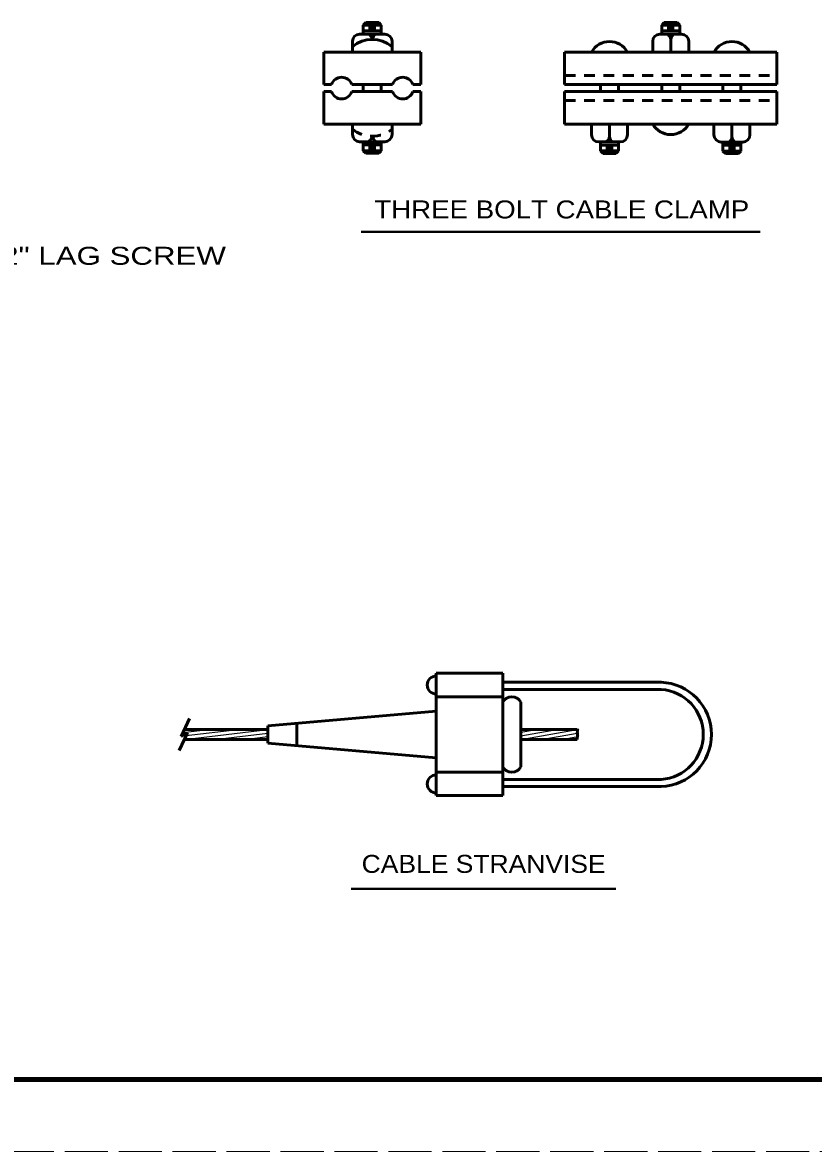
# Model space of a CAD drawing. Extents: x 12366 to 13046, y 9129 to 9570.
# Drawn here: x 12636.6 to 12746.6, y 9129.5 to 9286.4 of the extents above; entities that cross this region are included whole.
import ezdxf
from ezdxf.enums import TextEntityAlignment as Align

# ---------------------------------------------------------------- set-up
doc = ezdxf.new("R2010")
doc.units = 0
doc.linetypes.add('LONG_DASHED', pattern=[7.5, 6, -1.5])
doc.linetypes.add('SHORT_DASHED', pattern=[2.7, 1.5, -1.2])
doc.layers.add('1', color=7, linetype='Continuous', lineweight=53)
doc.layers.add('61', color=7, linetype='Continuous', lineweight=35)

msp = doc.modelspace()

# ---------------------------------------------------------------- linework, layer by layer
at = {"layer": '1'}
for p, q in [((12683.99, 9286.07), (12684.344, 9286.423)), ((12683.99, 9286.07), (12686.49, 9286.07)), ((12683.99, 9284.82), (12683.99, 9286.07)), ((12684.344, 9286.423), (12686.137, 9286.423)), ((12684.74, 9285.67), (12685.74, 9285.67)), ((12686.49, 9286.07), (12686.137, 9286.423)), ((12686.49, 9284.82), (12686.49, 9286.07)), ((12725.49, 9286.07), (12725.844, 9286.423)), ((12725.49, 9284.82), (12725.49, 9286.07)), ((12725.49, 9286.07), (12727.99, 9286.07)), ((12725.844, 9286.423), (12727.637, 9286.423)), ((12726.24, 9285.67), (12727.24, 9285.67)), ((12727.99, 9286.07), (12727.637, 9286.423)), ((12727.99, 9284.82), (12727.99, 9286.07)), ((12683.49, 9284.82), (12686.99, 9284.82)), ((12683.99, 9285.27), (12686.49, 9285.27)), ((12726.74, 9284.82), (12725.24, 9284.82)), ((12725.49, 9285.27), (12727.99, 9285.27)), ((12726.74, 9284.82), (12728.24, 9284.82)), ((12726.74, 9282.32), (12726.74, 9284.07)), ((12682.49, 9282.32), (12682.49, 9283.82)), ((12687.99, 9282.32), (12687.99, 9283.82)), ((12724.24, 9282.32), (12724.24, 9283.82)), ((12729.24, 9282.32), (12729.24, 9283.82)), ((12678.49, 9282.32), (12691.99, 9282.32)), ((12678.49, 9282.32), (12678.49, 9277.82)), ((12691.99, 9282.32), (12691.99, 9277.82)), ((12711.99, 9282.32), (12741.49, 9282.32)), ((12711.99, 9282.32), (12711.99, 9277.82)), ((12741.49, 9282.32), (12741.49, 9277.82)), ((12678.49, 9277.82), (12679.572, 9277.82)), ((12682.4, 9277.82), (12688.07, 9277.82)), ((12683.99, 9276.82), (12683.99, 9277.82)), ((12686.49, 9276.82), (12686.49, 9277.82)), ((12691.99, 9277.82), (12690.896, 9277.82)), ((12711.99, 9277.82), (12741.49, 9277.82)), ((12716.99, 9276.82), (12716.99, 9277.82)), ((12719.49, 9276.82), (12719.49, 9277.82)), ((12725.49, 9276.82), (12725.49, 9277.82)), ((12727.99, 9276.82), (12727.99, 9277.82)), ((12733.99, 9276.82), (12733.99, 9277.82)), ((12736.49, 9276.82), (12736.49, 9277.82)), ((12678.49, 9272.32), (12678.49, 9276.82)), ((12678.49, 9276.82), (12679.571, 9276.82)), ((12682.4, 9276.82), (12688.068, 9276.82)), ((12691.99, 9276.82), (12690.898, 9276.82)), ((12691.99, 9272.32), (12691.99, 9276.82)), ((12711.99, 9276.82), (12711.99, 9272.32)), ((12741.49, 9276.82), (12741.49, 9272.32)), ((12678.49, 9272.32), (12691.99, 9272.32)), ((12682.49, 9272.361), (12682.49, 9270.861)), ((12687.99, 9272.361), (12687.99, 9270.861)), ((12711.99, 9272.32), (12741.49, 9272.32)), ((12715.727, 9272.327), (12715.727, 9270.827)), ((12718.227, 9272.327), (12718.227, 9270.577)), ((12720.727, 9272.327), (12720.727, 9270.827)), ((12732.759, 9272.316), (12732.759, 9270.816)), ((12735.259, 9272.316), (12735.259, 9270.566)), ((12737.759, 9272.316), (12737.759, 9270.816)), ((12683.49, 9269.861), (12686.99, 9269.861)), ((12683.99, 9269.861), (12683.99, 9268.611)), ((12686.49, 9269.861), (12686.49, 9268.611)), ((12683.99, 9269.411), (12686.49, 9269.411)), ((12683.99, 9268.611), (12684.344, 9268.257)), ((12683.99, 9268.611), (12686.49, 9268.611)), ((12684.74, 9269.011), (12685.74, 9269.011)), ((12686.49, 9268.611), (12686.137, 9268.257)), ((12718.227, 9269.827), (12716.727, 9269.827)), ((12716.977, 9269.827), (12716.977, 9268.577)), ((12716.977, 9269.377), (12719.477, 9269.377)), ((12716.977, 9268.577), (12717.33, 9268.223)), ((12716.977, 9268.577), (12719.477, 9268.577)), ((12717.727, 9268.977), (12718.727, 9268.977)), ((12718.227, 9269.827), (12719.727, 9269.827)), ((12719.477, 9268.577), (12719.123, 9268.223)), ((12719.477, 9269.827), (12719.477, 9268.577)), ((12735.259, 9269.816), (12733.759, 9269.816)), ((12734.009, 9269.816), (12734.009, 9268.566)), ((12734.009, 9269.366), (12736.509, 9269.366)), ((12734.009, 9268.566), (12734.363, 9268.213)), ((12734.009, 9268.566), (12736.509, 9268.566)), ((12734.759, 9268.966), (12735.759, 9268.966)), ((12735.259, 9269.816), (12736.759, 9269.816)), ((12736.509, 9268.566), (12736.156, 9268.213)), ((12736.509, 9269.816), (12736.509, 9268.566)), ((12684.344, 9268.257), (12686.137, 9268.257)), ((12717.33, 9268.223), (12719.123, 9268.223)), ((12734.363, 9268.213), (12736.156, 9268.213)), ((12694.145, 9195.961), (12703.395, 9195.961)), ((12694.145, 9192.711), (12694.145, 9195.961)), ((12703.395, 9178.961), (12703.395, 9195.961)), ((12703.395, 9194.711), (12725.395, 9194.711)), ((12703.395, 9193.711), (12725.395, 9193.711)), ((12694.145, 9192.711), (12703.395, 9192.711)), ((12705.895, 9182.961), (12705.895, 9191.961)), ((12694.145, 9190.711), (12670.735, 9188.663)), ((12658.676, 9187.197), (12659.838, 9189.689)), ((12670.735, 9188.663), (12670.735, 9186.259)), ((12674.735, 9189.013), (12674.735, 9185.909)), ((12658.416, 9185.214), (12659.578, 9187.707)), ((12658.676, 9187.197), (12659.578, 9187.707)), ((12670.735, 9188.163), (12659.126, 9188.163)), ((12670.735, 9186.759), (12659.136, 9186.759)), ((12705.895, 9188.163), (12713.735, 9188.163)), ((12705.895, 9186.759), (12713.735, 9186.759)), ((12694.145, 9184.211), (12670.735, 9186.259)), ((12694.145, 9182.211), (12703.395, 9182.211)), ((12703.395, 9181.211), (12725.395, 9181.211)), ((12694.145, 9178.961), (12703.395, 9178.961)), ((12703.395, 9180.211), (12725.395, 9180.211))]:
    msp.add_line(p, q, dxfattribs=at)
at = {"layer": '1', "lineweight": 13}
msp.add_line((12682.407, 9277.82), (12682.49, 9277.82), dxfattribs=at)
at = {"layer": '1', "linetype": 'SHORT_DASHED'}
for p, q in [((12711.99, 9279.07), (12741.49, 9279.07)), ((12711.99, 9275.57), (12741.49, 9275.57))]:
    msp.add_line(p, q, dxfattribs=at)
at = {"layer": '1', "lineweight": 40}
for p, q in [((12683.688, 9257.318), (12739.159, 9257.318)), ((12682.314, 9166.003), (12719.09, 9166.003))]:
    msp.add_line(p, q, dxfattribs=at)
at = {"layer": '1', "lineweight": 25}
for p, q in [((12658.929, 9187.741), (12662.412, 9188.163)), ((12659.136, 9186.759), (12670.735, 9188.163)), ((12659.385, 9187.293), (12666.573, 9188.163)), ((12663.298, 9186.759), (12670.735, 9187.659)), ((12667.459, 9186.759), (12670.735, 9187.155)), ((12705.895, 9186.759), (12713.735, 9188.163)), ((12705.895, 9187.775), (12708.061, 9188.163)), ((12705.895, 9187.267), (12710.898, 9188.163)), ((12708.732, 9186.759), (12713.721, 9187.652)), ((12711.569, 9186.759), (12713.807, 9187.16))]:
    msp.add_line(p, q, dxfattribs=at)
at = {"layer": '1'}
for points in [[(12711.99, 9276.82), (12716.99, 9276.82), (12719.49, 9276.82), (12733.99, 9276.82)], [(12733.99, 9276.82), (12736.49, 9276.82), (12741.49, 9276.82)], [(12694.145, 9178.961), (12694.145, 9182.211), (12694.145, 9192.711)]]:
    msp.add_lwpolyline(points, dxfattribs=at)
for centre, radius, start, end in [((12683.49, 9283.82), 1, 90, 180), ((12685.24, 9279.789), 4.281, 50.03379, 129.96621), ((12683.913, 9283.727), 1.371, 14.49718, 52.88295), ((12686.561, 9283.727), 1.371, 127.11705, 165.50282), ((12686.99, 9283.82), 1, 0, 90), ((12725.24, 9283.82), 1, 90, 180), ((12725.86, 9284.025), 0.882, 2.94427, 64.43586), ((12727.621, 9284.025), 0.882, 115.56414, 177.05572), ((12728.24, 9283.82), 1, 0, 90), ((12718.227, 9280.933), 2.862, 29.14172, 150.85828), ((12735.259, 9280.922), 2.862, 29.14172, 150.85828), ((12680.986, 9277.319), 1.5, 19.49795, 160.50177), ((12689.483, 9277.317), 1.5, 19.58943, 160.41041), ((12680.986, 9277.319), 1.5, 199.44421, 340.55538), ((12689.483, 9277.317), 1.5, 199.35299, 340.6469), ((12726.74, 9273.714), 2.862, 209.14172, 330.85828), ((12683.49, 9270.861), 1, 180, 270), ((12683.913, 9270.954), 1.371, 307.11705, 345.50282), ((12686.561, 9270.954), 1.371, 194.49718, 232.88295), ((12686.99, 9270.861), 1, 270, 0), ((12716.727, 9270.827), 1, 180, 270), ((12717.346, 9270.622), 0.882, 295.56414, 357.05572), ((12719.107, 9270.622), 0.882, 182.94427, 244.43586), ((12719.727, 9270.827), 1, 270, 0), ((12733.759, 9270.816), 1, 180, 270), ((12734.379, 9270.611), 0.882, 295.56414, 357.05572), ((12736.14, 9270.611), 0.882, 182.94427, 244.43586), ((12736.759, 9270.816), 1, 270, 0), ((12694.145, 9194.336), 1.25, 90, 270), ((12725.141, 9187.461), 7.255, 272.01017, 87.98983), ((12725.002, 9187.461), 6.262, 273.59778, 86.40223), ((12704.645, 9191.294), 1.417, 28.07249, 151.92751), ((12704.645, 9183.626), 1.417, 208.07249, 331.92751), ((12694.145, 9180.586), 1.25, 90, 270)]:
    msp.add_arc(centre, radius, start, end, dxfattribs=at)
at = {"layer": '1', "lineweight": 13}
msp.add_arc((12680.986, 9277.319), 1.5, 199.26221, 340.15338, dxfattribs=at)
at = {"layer": '1', "linetype": 'SHORT_DASHED'}
msp.add_arc((12685.24, 9274.892), 4.281, 230.03379, 309.96621, dxfattribs=at)
at = {"layer": '1'}
msp.add_spline([(12713.735, 9188.163), (12713.818, 9188.028), (12713.754, 9187.932), (12713.775, 9187.783), (12713.722, 9187.655), (12713.807, 9187.548), (12713.764, 9187.452), (12713.796, 9187.27), (12713.786, 9187.121), (12713.722, 9187.003), (12713.732, 9186.939), (12713.735, 9186.759)], degree=3, dxfattribs=at)
at = {"layer": '61', "lineweight": 158}
msp.add_line((13035.052, 9139.493), (12395.992, 9139.513), dxfattribs=at)
at = {"layer": '61', "linetype": 'LONG_DASHED', "lineweight": 13}
msp.add_line((13045.992, 9129.513), (12365.932, 9129.493), dxfattribs=at)

# ---------------------------------------------------------------- texts
at = {"layer": '1'}
for s, width, p in [('THREE BOLT CABLE CLAMP', 1.15, (12711.593, 9259.197)), ('CABLE STRANVISE', 1.1, (12700.729, 9168.218))]:
    msp.add_text(s, height=2.5, dxfattribs=dict(at, width=width)).set_placement(p, align=Align.CENTER)
at = {"layer": '1', "width": 1.3}
msp.add_text('3/8"X2-1/2" LAG SCREW', height=2.5, dxfattribs=at).set_placement((12615.676, 9252.751))

doc.saveas('drawing.dxf')
